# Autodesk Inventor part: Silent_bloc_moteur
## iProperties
Created: 2011-01
Part Number: Silent_bloc_moteur
Document SubType Name: Modeling
Designer: eric
Density: 1 g/cm^3
Mass: 0.123076 g
Surface Area: 2.67964 cm^2
Volume: 0.123076 cm^3
Author: eric
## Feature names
1. Base1
